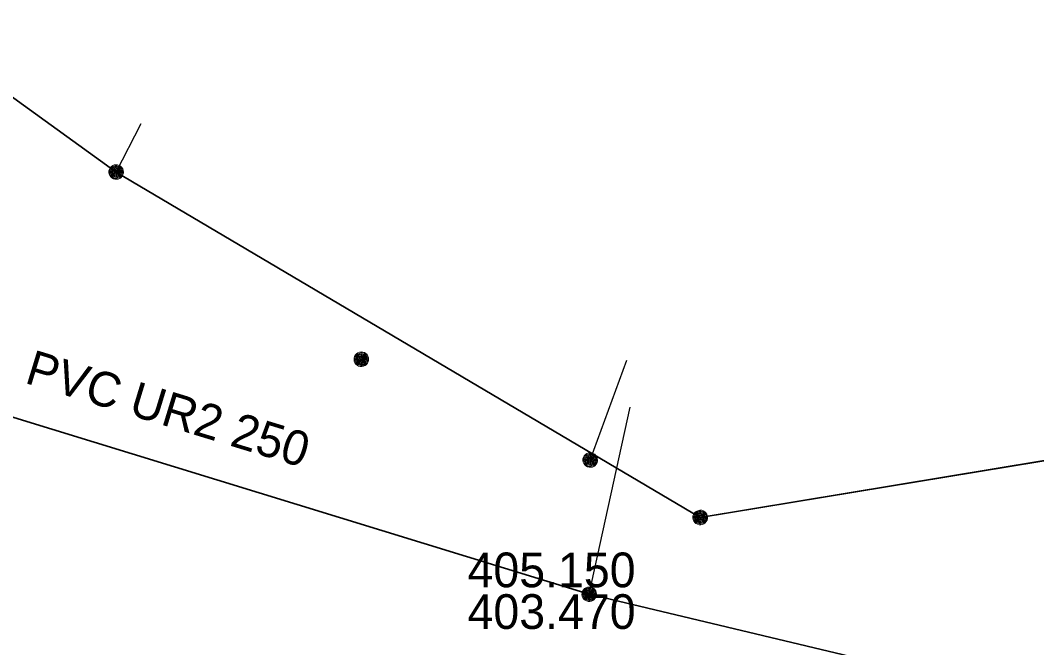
# Model space of a CAD drawing. Extents: x -873619 to -867639, y -1015082 to -1012326.
# Drawn here: x -868080.46 to -868048.3, y -1012848.52 to -1012828.66 of the extents above; entities that cross this region are included whole.
import ezdxf

# ---------------------------------------------------------------- set-up
doc = ezdxf.new("R2010")
doc.units = 0
doc.header["$LTSCALE"] = 0.44
for name, color, linetype, lineweight in [('1', 7, 'Continuous', 13), ('12', 7, 'Continuous', 13), ('21', 7, 'Continuous', 35), ('23', 7, 'Continuous', 25), ('3', 7, 'Continuous', 25), ('32', 7, 'Continuous', 13)]:
    doc.layers.add(name, color=color, linetype=linetype, lineweight=lineweight)

msp = doc.modelspace()

# ---------------------------------------------------------------- linework, layer by layer
at = {"layer": '1', "lineweight": 35}
for points in [[(-867974.611, -1012725.697), (-867976.949, -1012730.385), (-867980.624, -1012763.205), (-867983.112, -1012775.195), (-867978.719, -1012795.525), (-867979.823, -1012805.464), (-867997.768, -1012829.005), (-868011.042, -1012836.499), (-868058.95, -1012844.4), (-868077.43, -1012833.46), (-868085.171, -1012827.86)], [(-868058.95, -1012844.4), (-868077.43, -1012833.46), (-868085.171, -1012827.86), (-868086.94, -1012814.56)], [(-867997.768, -1012829.005), (-868011.041, -1012836.459), (-868058.95, -1012844.4)]]:
    msp.add_lwpolyline(points, dxfattribs=at)
at = {"layer": '12'}
for points in [[(-868077.199, -1012833.46), (-868077.205, -1012833.408), (-868077.222, -1012833.358), (-868077.251, -1012833.314), (-868077.288, -1012833.277), (-868077.333, -1012833.25), (-868077.383, -1012833.233), (-868077.436, -1012833.229), (-868077.488, -1012833.236), (-868077.537, -1012833.255), (-868077.58, -1012833.284), (-868077.616, -1012833.323), (-868077.642, -1012833.368), (-868077.658, -1012833.419), (-868077.661, -1012833.471), (-868077.653, -1012833.523), (-868077.633, -1012833.572), (-868077.602, -1012833.615), (-868077.563, -1012833.649), (-868077.517, -1012833.675), (-868077.466, -1012833.689), (-868077.413, -1012833.691), (-868077.362, -1012833.681), (-868077.314, -1012833.66), (-868077.271, -1012833.629), (-868077.237, -1012833.588), (-868077.213, -1012833.542), (-868077.201, -1012833.491)], [(-868077.229, -1012833.46), (-868077.235, -1012833.411), (-868077.252, -1012833.365), (-868077.28, -1012833.325), (-868077.317, -1012833.293), (-868077.361, -1012833.271), (-868077.409, -1012833.26), (-868077.458, -1012833.26), (-868077.505, -1012833.273), (-868077.548, -1012833.297), (-868077.584, -1012833.33), (-868077.611, -1012833.371), (-868077.627, -1012833.418), (-868077.631, -1012833.467), (-868077.624, -1012833.515), (-868077.605, -1012833.56), (-868077.575, -1012833.6), (-868077.537, -1012833.631), (-868077.493, -1012833.651), (-868077.445, -1012833.661), (-868077.396, -1012833.659), (-868077.349, -1012833.644), (-868077.306, -1012833.619), (-868077.272, -1012833.585), (-868077.246, -1012833.543), (-868077.232, -1012833.496)], [(-868077.259, -1012833.46), (-868077.265, -1012833.415), (-868077.282, -1012833.373), (-868077.31, -1012833.338), (-868077.346, -1012833.311), (-868077.388, -1012833.294), (-868077.433, -1012833.289), (-868077.478, -1012833.295), (-868077.519, -1012833.314), (-868077.554, -1012833.342), (-868077.581, -1012833.379), (-868077.597, -1012833.421), (-868077.601, -1012833.466), (-868077.594, -1012833.511), (-868077.575, -1012833.552), (-868077.546, -1012833.586), (-868077.509, -1012833.612), (-868077.466, -1012833.628), (-868077.421, -1012833.631), (-868077.376, -1012833.623), (-868077.336, -1012833.603), (-868077.302, -1012833.574), (-868077.276, -1012833.536), (-868077.262, -1012833.493)], [(-868077.289, -1012833.46), (-868077.294, -1012833.419), (-868077.312, -1012833.382), (-868077.339, -1012833.351), (-868077.374, -1012833.33), (-868077.414, -1012833.319), (-868077.455, -1012833.321), (-868077.494, -1012833.334), (-868077.528, -1012833.358), (-868077.553, -1012833.39), (-868077.568, -1012833.428), (-868077.571, -1012833.469), (-868077.563, -1012833.509), (-868077.543, -1012833.545), (-868077.514, -1012833.574), (-868077.477, -1012833.593), (-868077.437, -1012833.601), (-868077.396, -1012833.597), (-868077.358, -1012833.582), (-868077.326, -1012833.556), (-868077.303, -1012833.522), (-868077.29, -1012833.483)], [(-868077.319, -1012833.46), (-868077.324, -1012833.424), (-868077.342, -1012833.392), (-868077.368, -1012833.367), (-868077.402, -1012833.352), (-868077.438, -1012833.349), (-868077.473, -1012833.357), (-868077.504, -1012833.377), (-868077.527, -1012833.405), (-868077.54, -1012833.439), (-868077.54, -1012833.476), (-868077.529, -1012833.511), (-868077.508, -1012833.54), (-868077.478, -1012833.561), (-868077.443, -1012833.571), (-868077.406, -1012833.569), (-868077.372, -1012833.555), (-868077.345, -1012833.532), (-868077.326, -1012833.5), (-868077.319, -1012833.465)], [(-868077.349, -1012833.46), (-868077.354, -1012833.429), (-868077.371, -1012833.403), (-868077.397, -1012833.386), (-868077.427, -1012833.379), (-868077.458, -1012833.383), (-868077.485, -1012833.4), (-868077.503, -1012833.424), (-868077.511, -1012833.455), (-868077.507, -1012833.485), (-868077.492, -1012833.513), (-868077.468, -1012833.532), (-868077.438, -1012833.541), (-868077.407, -1012833.538), (-868077.379, -1012833.524), (-868077.359, -1012833.5), (-868077.349, -1012833.471)], [(-868077.379, -1012833.46), (-868077.384, -1012833.436), (-868077.401, -1012833.418), (-868077.424, -1012833.409), (-868077.448, -1012833.412), (-868077.469, -1012833.426), (-868077.48, -1012833.448), (-868077.48, -1012833.473), (-868077.468, -1012833.494), (-868077.448, -1012833.508), (-868077.423, -1012833.511), (-868077.4, -1012833.502), (-868077.384, -1012833.484)], [(-868077.409, -1012833.46), (-868077.414, -1012833.445), (-868077.429, -1012833.439), (-868077.444, -1012833.443), (-868077.451, -1012833.457), (-868077.447, -1012833.472), (-868077.434, -1012833.481), (-868077.419, -1012833.478), (-868077.409, -1012833.466)], [(-868062.199, -1012842.58), (-868062.205, -1012842.528), (-868062.222, -1012842.478), (-868062.251, -1012842.434), (-868062.288, -1012842.397), (-868062.333, -1012842.37), (-868062.383, -1012842.353), (-868062.436, -1012842.349), (-868062.488, -1012842.356), (-868062.537, -1012842.375), (-868062.58, -1012842.404), (-868062.616, -1012842.443), (-868062.642, -1012842.488), (-868062.658, -1012842.539), (-868062.661, -1012842.591), (-868062.653, -1012842.643), (-868062.633, -1012842.692), (-868062.602, -1012842.735), (-868062.563, -1012842.769), (-868062.517, -1012842.795), (-868062.466, -1012842.809), (-868062.413, -1012842.811), (-868062.362, -1012842.801), (-868062.314, -1012842.78), (-868062.271, -1012842.749), (-868062.237, -1012842.708), (-868062.213, -1012842.662), (-868062.201, -1012842.611)], [(-868062.229, -1012842.58), (-868062.235, -1012842.531), (-868062.252, -1012842.485), (-868062.28, -1012842.445), (-868062.317, -1012842.413), (-868062.361, -1012842.391), (-868062.409, -1012842.38), (-868062.458, -1012842.38), (-868062.505, -1012842.393), (-868062.548, -1012842.417), (-868062.584, -1012842.45), (-868062.611, -1012842.491), (-868062.627, -1012842.538), (-868062.631, -1012842.587), (-868062.624, -1012842.635), (-868062.605, -1012842.68), (-868062.575, -1012842.72), (-868062.537, -1012842.751), (-868062.493, -1012842.771), (-868062.445, -1012842.781), (-868062.396, -1012842.779), (-868062.349, -1012842.764), (-868062.306, -1012842.739), (-868062.272, -1012842.705), (-868062.246, -1012842.663), (-868062.232, -1012842.616)], [(-868062.259, -1012842.58), (-868062.265, -1012842.535), (-868062.282, -1012842.493), (-868062.31, -1012842.458), (-868062.346, -1012842.431), (-868062.388, -1012842.414), (-868062.433, -1012842.409), (-868062.478, -1012842.415), (-868062.519, -1012842.434), (-868062.554, -1012842.462), (-868062.581, -1012842.499), (-868062.597, -1012842.541), (-868062.601, -1012842.586), (-868062.594, -1012842.631), (-868062.575, -1012842.672), (-868062.546, -1012842.706), (-868062.509, -1012842.732), (-868062.466, -1012842.748), (-868062.421, -1012842.751), (-868062.376, -1012842.743), (-868062.336, -1012842.723), (-868062.302, -1012842.694), (-868062.276, -1012842.656), (-868062.262, -1012842.613)], [(-868062.289, -1012842.58), (-868062.294, -1012842.539), (-868062.312, -1012842.502), (-868062.339, -1012842.471), (-868062.374, -1012842.45), (-868062.414, -1012842.439), (-868062.455, -1012842.441), (-868062.494, -1012842.454), (-868062.528, -1012842.478), (-868062.553, -1012842.51), (-868062.568, -1012842.548), (-868062.571, -1012842.589), (-868062.563, -1012842.629), (-868062.543, -1012842.665), (-868062.514, -1012842.694), (-868062.477, -1012842.713), (-868062.437, -1012842.721), (-868062.396, -1012842.717), (-868062.358, -1012842.702), (-868062.326, -1012842.676), (-868062.303, -1012842.642), (-868062.29, -1012842.603)], [(-868062.319, -1012842.58), (-868062.324, -1012842.544), (-868062.342, -1012842.512), (-868062.368, -1012842.487), (-868062.402, -1012842.472), (-868062.438, -1012842.469), (-868062.473, -1012842.477), (-868062.504, -1012842.497), (-868062.527, -1012842.525), (-868062.54, -1012842.559), (-868062.54, -1012842.596), (-868062.529, -1012842.631), (-868062.508, -1012842.66), (-868062.478, -1012842.681), (-868062.443, -1012842.691), (-868062.406, -1012842.689), (-868062.372, -1012842.675), (-868062.345, -1012842.652), (-868062.326, -1012842.62), (-868062.319, -1012842.585)], [(-868062.349, -1012842.58), (-868062.354, -1012842.549), (-868062.371, -1012842.523), (-868062.397, -1012842.506), (-868062.427, -1012842.499), (-868062.458, -1012842.503), (-868062.485, -1012842.52), (-868062.503, -1012842.544), (-868062.511, -1012842.575), (-868062.507, -1012842.605), (-868062.492, -1012842.633), (-868062.468, -1012842.652), (-868062.438, -1012842.661), (-868062.407, -1012842.658), (-868062.379, -1012842.644), (-868062.359, -1012842.62), (-868062.349, -1012842.591)], [(-868062.379, -1012842.58), (-868062.384, -1012842.556), (-868062.401, -1012842.538), (-868062.424, -1012842.529), (-868062.448, -1012842.532), (-868062.469, -1012842.546), (-868062.48, -1012842.568), (-868062.48, -1012842.593), (-868062.468, -1012842.614), (-868062.448, -1012842.628), (-868062.423, -1012842.631), (-868062.4, -1012842.622), (-868062.384, -1012842.604)], [(-868062.409, -1012842.58), (-868062.414, -1012842.565), (-868062.429, -1012842.559), (-868062.444, -1012842.563), (-868062.451, -1012842.577), (-868062.447, -1012842.592), (-868062.434, -1012842.601), (-868062.419, -1012842.598), (-868062.409, -1012842.586)], [(-868058.718, -1012844.4), (-868058.725, -1012844.348), (-868058.742, -1012844.298), (-868058.771, -1012844.254), (-868058.808, -1012844.217), (-868058.853, -1012844.19), (-868058.902, -1012844.173), (-868058.956, -1012844.169), (-868059.007, -1012844.176), (-868059.056, -1012844.195), (-868059.1, -1012844.224), (-868059.136, -1012844.263), (-868059.162, -1012844.308), (-868059.178, -1012844.359), (-868059.181, -1012844.411), (-868059.173, -1012844.463), (-868059.152, -1012844.512), (-868059.122, -1012844.555), (-868059.083, -1012844.589), (-868059.037, -1012844.615), (-868058.985, -1012844.629), (-868058.933, -1012844.631), (-868058.882, -1012844.621), (-868058.833, -1012844.6), (-868058.791, -1012844.569), (-868058.757, -1012844.528), (-868058.733, -1012844.482), (-868058.72, -1012844.431)], [(-868058.749, -1012844.4), (-868058.755, -1012844.351), (-868058.772, -1012844.305), (-868058.799, -1012844.265), (-868058.837, -1012844.233), (-868058.88, -1012844.211), (-868058.929, -1012844.2), (-868058.978, -1012844.2), (-868059.024, -1012844.213), (-868059.068, -1012844.237), (-868059.103, -1012844.27), (-868059.13, -1012844.311), (-868059.147, -1012844.358), (-868059.151, -1012844.407), (-868059.144, -1012844.455), (-868059.125, -1012844.5), (-868059.095, -1012844.54), (-868059.056, -1012844.571), (-868059.012, -1012844.591), (-868058.965, -1012844.601), (-868058.916, -1012844.599), (-868058.869, -1012844.584), (-868058.826, -1012844.559), (-868058.791, -1012844.525), (-868058.766, -1012844.483), (-868058.752, -1012844.436)], [(-868058.779, -1012844.4), (-868058.784, -1012844.355), (-868058.801, -1012844.313), (-868058.83, -1012844.278), (-868058.865, -1012844.251), (-868058.907, -1012844.234), (-868058.953, -1012844.229), (-868058.997, -1012844.235), (-868059.039, -1012844.254), (-868059.073, -1012844.282), (-868059.1, -1012844.319), (-868059.117, -1012844.361), (-868059.12, -1012844.406), (-868059.114, -1012844.451), (-868059.095, -1012844.492), (-868059.066, -1012844.526), (-868059.029, -1012844.552), (-868058.985, -1012844.568), (-868058.941, -1012844.571), (-868058.896, -1012844.563), (-868058.855, -1012844.543), (-868058.821, -1012844.514), (-868058.796, -1012844.476), (-868058.782, -1012844.433)], [(-868058.809, -1012844.4), (-868058.813, -1012844.359), (-868058.831, -1012844.322), (-868058.858, -1012844.291), (-868058.894, -1012844.27), (-868058.934, -1012844.259), (-868058.975, -1012844.261), (-868059.014, -1012844.274), (-868059.048, -1012844.298), (-868059.073, -1012844.33), (-868059.088, -1012844.368), (-868059.09, -1012844.409), (-868059.083, -1012844.449), (-868059.063, -1012844.485), (-868059.034, -1012844.514), (-868058.997, -1012844.533), (-868058.956, -1012844.541), (-868058.916, -1012844.537), (-868058.877, -1012844.522), (-868058.845, -1012844.496), (-868058.823, -1012844.462), (-868058.809, -1012844.423)], [(-868058.838, -1012844.4), (-868058.843, -1012844.364), (-868058.862, -1012844.332), (-868058.887, -1012844.307), (-868058.921, -1012844.292), (-868058.958, -1012844.289), (-868058.992, -1012844.297), (-868059.024, -1012844.317), (-868059.046, -1012844.345), (-868059.059, -1012844.379), (-868059.059, -1012844.416), (-868059.049, -1012844.451), (-868059.027, -1012844.48), (-868058.997, -1012844.501), (-868058.963, -1012844.511), (-868058.926, -1012844.509), (-868058.892, -1012844.495), (-868058.865, -1012844.472), (-868058.845, -1012844.44), (-868058.838, -1012844.405)], [(-868058.869, -1012844.4), (-868058.874, -1012844.369), (-868058.891, -1012844.343), (-868058.916, -1012844.326), (-868058.946, -1012844.319), (-868058.978, -1012844.323), (-868059.005, -1012844.34), (-868059.022, -1012844.364), (-868059.031, -1012844.395), (-868059.027, -1012844.425), (-868059.012, -1012844.453), (-868058.987, -1012844.472), (-868058.958, -1012844.481), (-868058.926, -1012844.478), (-868058.899, -1012844.464), (-868058.879, -1012844.44), (-868058.869, -1012844.411)], [(-868058.899, -1012844.4), (-868058.904, -1012844.376), (-868058.921, -1012844.358), (-868058.943, -1012844.349), (-868058.968, -1012844.352), (-868058.989, -1012844.366), (-868059, -1012844.388), (-868059, -1012844.413), (-868058.987, -1012844.434), (-868058.968, -1012844.448), (-868058.943, -1012844.451), (-868058.919, -1012844.442), (-868058.904, -1012844.424)], [(-868058.929, -1012844.4), (-868058.934, -1012844.385), (-868058.948, -1012844.379), (-868058.963, -1012844.383), (-868058.97, -1012844.397), (-868058.967, -1012844.412), (-868058.953, -1012844.421), (-868058.938, -1012844.418), (-868058.929, -1012844.406)]]:
    msp.add_lwpolyline(points, close=True, dxfattribs=at)
at = {"layer": '21'}
msp.add_lwpolyline([(-868134.19, -1012752.63), (-868112.27, -1012769.62), (-868107.42, -1012773.25), (-868101.75, -1012777.58), (-868093.15, -1012793.25), (-868087.37, -1012839.18), (-868062.459, -1012846.83), (-868020.28, -1012856.9)], dxfattribs=at)
at = {"layer": '23'}
msp.add_line((-868062.459, -1012846.83), (-868061.17, -1012840.91), dxfattribs=at)
at = {"layer": '3'}
for p, q in [((-868077.43, -1012833.46), (-868076.634, -1012831.92)), ((-868062.43, -1012842.58), (-868061.266, -1012839.421))]:
    msp.add_line(p, q, dxfattribs=at)
at = {"layer": '32'}
for points in [[(-868069.44, -1012839.389), (-868069.446, -1012839.337), (-868069.463, -1012839.287), (-868069.492, -1012839.243), (-868069.529, -1012839.206), (-868069.574, -1012839.179), (-868069.624, -1012839.162), (-868069.677, -1012839.158), (-868069.728, -1012839.165), (-868069.777, -1012839.184), (-868069.821, -1012839.213), (-868069.857, -1012839.252), (-868069.883, -1012839.297), (-868069.899, -1012839.348), (-868069.902, -1012839.4), (-868069.894, -1012839.452), (-868069.874, -1012839.501), (-868069.843, -1012839.544), (-868069.804, -1012839.578), (-868069.758, -1012839.604), (-868069.706, -1012839.618), (-868069.654, -1012839.62), (-868069.603, -1012839.61), (-868069.554, -1012839.589), (-868069.512, -1012839.558), (-868069.478, -1012839.517), (-868069.454, -1012839.471), (-868069.441, -1012839.42)], [(-868069.47, -1012839.389), (-868069.476, -1012839.34), (-868069.493, -1012839.294), (-868069.521, -1012839.254), (-868069.558, -1012839.222), (-868069.602, -1012839.2), (-868069.65, -1012839.189), (-868069.699, -1012839.189), (-868069.745, -1012839.202), (-868069.789, -1012839.226), (-868069.825, -1012839.259), (-868069.852, -1012839.3), (-868069.868, -1012839.347), (-868069.872, -1012839.396), (-868069.865, -1012839.444), (-868069.846, -1012839.489), (-868069.816, -1012839.529), (-868069.777, -1012839.56), (-868069.733, -1012839.58), (-868069.686, -1012839.59), (-868069.637, -1012839.588), (-868069.59, -1012839.573), (-868069.547, -1012839.548), (-868069.512, -1012839.514), (-868069.487, -1012839.472), (-868069.473, -1012839.425)], [(-868069.5, -1012839.389), (-868069.505, -1012839.344), (-868069.522, -1012839.302), (-868069.551, -1012839.267), (-868069.587, -1012839.24), (-868069.629, -1012839.223), (-868069.674, -1012839.218), (-868069.718, -1012839.224), (-868069.76, -1012839.243), (-868069.794, -1012839.271), (-868069.821, -1012839.308), (-868069.838, -1012839.35), (-868069.842, -1012839.395), (-868069.835, -1012839.44), (-868069.816, -1012839.481), (-868069.787, -1012839.515), (-868069.75, -1012839.541), (-868069.706, -1012839.557), (-868069.662, -1012839.56), (-868069.617, -1012839.552), (-868069.576, -1012839.532), (-868069.543, -1012839.503), (-868069.517, -1012839.465), (-868069.503, -1012839.422)], [(-868069.53, -1012839.389), (-868069.534, -1012839.348), (-868069.553, -1012839.311), (-868069.58, -1012839.28), (-868069.615, -1012839.259), (-868069.655, -1012839.248), (-868069.696, -1012839.25), (-868069.735, -1012839.263), (-868069.769, -1012839.287), (-868069.794, -1012839.319), (-868069.809, -1012839.357), (-868069.811, -1012839.398), (-868069.804, -1012839.438), (-868069.784, -1012839.474), (-868069.755, -1012839.503), (-868069.718, -1012839.522), (-868069.678, -1012839.53), (-868069.637, -1012839.526), (-868069.598, -1012839.511), (-868069.566, -1012839.485), (-868069.544, -1012839.451), (-868069.531, -1012839.412)], [(-868069.559, -1012839.389), (-868069.565, -1012839.353), (-868069.583, -1012839.321), (-868069.608, -1012839.296), (-868069.642, -1012839.281), (-868069.679, -1012839.278), (-868069.713, -1012839.286), (-868069.745, -1012839.306), (-868069.767, -1012839.334), (-868069.781, -1012839.368), (-868069.781, -1012839.405), (-868069.77, -1012839.44), (-868069.749, -1012839.469), (-868069.718, -1012839.49), (-868069.684, -1012839.5), (-868069.647, -1012839.498), (-868069.613, -1012839.484), (-868069.586, -1012839.461), (-868069.566, -1012839.429), (-868069.559, -1012839.394)], [(-868069.59, -1012839.389), (-868069.595, -1012839.358), (-868069.612, -1012839.332), (-868069.637, -1012839.315), (-868069.668, -1012839.308), (-868069.699, -1012839.312), (-868069.726, -1012839.329), (-868069.744, -1012839.353), (-868069.752, -1012839.384), (-868069.748, -1012839.414), (-868069.733, -1012839.442), (-868069.708, -1012839.461), (-868069.679, -1012839.47), (-868069.647, -1012839.467), (-868069.62, -1012839.453), (-868069.6, -1012839.429), (-868069.59, -1012839.4)], [(-868069.62, -1012839.389), (-868069.625, -1012839.365), (-868069.642, -1012839.347), (-868069.664, -1012839.338), (-868069.689, -1012839.341), (-868069.71, -1012839.355), (-868069.721, -1012839.377), (-868069.721, -1012839.402), (-868069.708, -1012839.423), (-868069.689, -1012839.437), (-868069.664, -1012839.44), (-868069.641, -1012839.431), (-868069.625, -1012839.413)], [(-868069.65, -1012839.389), (-868069.655, -1012839.374), (-868069.669, -1012839.368), (-868069.684, -1012839.372), (-868069.691, -1012839.386), (-868069.688, -1012839.401), (-868069.674, -1012839.41), (-868069.659, -1012839.407), (-868069.65, -1012839.395)], [(-868062.23, -1012846.829), (-868062.236, -1012846.777), (-868062.253, -1012846.727), (-868062.282, -1012846.683), (-868062.319, -1012846.646), (-868062.364, -1012846.619), (-868062.414, -1012846.602), (-868062.467, -1012846.598), (-868062.519, -1012846.605), (-868062.568, -1012846.624), (-868062.611, -1012846.653), (-868062.647, -1012846.692), (-868062.673, -1012846.737), (-868062.689, -1012846.788), (-868062.692, -1012846.84), (-868062.684, -1012846.892), (-868062.664, -1012846.941), (-868062.633, -1012846.984), (-868062.594, -1012847.018), (-868062.548, -1012847.044), (-868062.497, -1012847.058), (-868062.444, -1012847.06), (-868062.393, -1012847.05), (-868062.345, -1012847.029), (-868062.302, -1012846.998), (-868062.268, -1012846.957), (-868062.244, -1012846.911), (-868062.232, -1012846.86)], [(-868062.26, -1012846.829), (-868062.266, -1012846.78), (-868062.283, -1012846.734), (-868062.311, -1012846.694), (-868062.348, -1012846.662), (-868062.392, -1012846.64), (-868062.44, -1012846.629), (-868062.489, -1012846.629), (-868062.536, -1012846.642), (-868062.579, -1012846.666), (-868062.615, -1012846.699), (-868062.642, -1012846.74), (-868062.658, -1012846.787), (-868062.662, -1012846.836), (-868062.655, -1012846.884), (-868062.636, -1012846.929), (-868062.606, -1012846.969), (-868062.568, -1012847), (-868062.524, -1012847.02), (-868062.476, -1012847.03), (-868062.427, -1012847.028), (-868062.38, -1012847.013), (-868062.337, -1012846.988), (-868062.303, -1012846.954), (-868062.277, -1012846.912), (-868062.263, -1012846.865)], [(-868062.29, -1012846.829), (-868062.296, -1012846.784), (-868062.313, -1012846.742), (-868062.341, -1012846.707), (-868062.377, -1012846.68), (-868062.419, -1012846.663), (-868062.464, -1012846.658), (-868062.509, -1012846.664), (-868062.55, -1012846.683), (-868062.585, -1012846.711), (-868062.612, -1012846.748), (-868062.628, -1012846.79), (-868062.632, -1012846.835), (-868062.625, -1012846.88), (-868062.606, -1012846.921), (-868062.577, -1012846.955), (-868062.54, -1012846.981), (-868062.497, -1012846.997), (-868062.452, -1012847), (-868062.407, -1012846.992), (-868062.367, -1012846.972), (-868062.333, -1012846.943), (-868062.307, -1012846.905), (-868062.293, -1012846.862)], [(-868062.32, -1012846.829), (-868062.325, -1012846.788), (-868062.343, -1012846.751), (-868062.37, -1012846.72), (-868062.405, -1012846.699), (-868062.445, -1012846.688), (-868062.486, -1012846.69), (-868062.525, -1012846.703), (-868062.559, -1012846.727), (-868062.584, -1012846.759), (-868062.599, -1012846.797), (-868062.602, -1012846.838), (-868062.594, -1012846.878), (-868062.574, -1012846.914), (-868062.545, -1012846.943), (-868062.508, -1012846.962), (-868062.468, -1012846.97), (-868062.427, -1012846.966), (-868062.389, -1012846.951), (-868062.357, -1012846.925), (-868062.334, -1012846.891), (-868062.321, -1012846.852)], [(-868062.35, -1012846.829), (-868062.355, -1012846.793), (-868062.373, -1012846.761), (-868062.399, -1012846.736), (-868062.433, -1012846.721), (-868062.469, -1012846.718), (-868062.504, -1012846.726), (-868062.535, -1012846.746), (-868062.558, -1012846.774), (-868062.571, -1012846.808), (-868062.571, -1012846.845), (-868062.56, -1012846.88), (-868062.539, -1012846.909), (-868062.509, -1012846.93), (-868062.474, -1012846.94), (-868062.437, -1012846.938), (-868062.403, -1012846.924), (-868062.376, -1012846.901), (-868062.357, -1012846.869), (-868062.35, -1012846.834)], [(-868062.38, -1012846.829), (-868062.385, -1012846.798), (-868062.402, -1012846.772), (-868062.428, -1012846.755), (-868062.458, -1012846.748), (-868062.489, -1012846.752), (-868062.516, -1012846.769), (-868062.534, -1012846.793), (-868062.542, -1012846.824), (-868062.538, -1012846.854), (-868062.523, -1012846.882), (-868062.499, -1012846.901), (-868062.469, -1012846.91), (-868062.438, -1012846.907), (-868062.41, -1012846.893), (-868062.39, -1012846.869), (-868062.38, -1012846.84)], [(-868062.41, -1012846.829), (-868062.415, -1012846.805), (-868062.432, -1012846.787), (-868062.455, -1012846.778), (-868062.479, -1012846.781), (-868062.5, -1012846.795), (-868062.511, -1012846.817), (-868062.511, -1012846.842), (-868062.499, -1012846.863), (-868062.479, -1012846.877), (-868062.454, -1012846.88), (-868062.431, -1012846.871), (-868062.415, -1012846.853)], [(-868062.44, -1012846.829), (-868062.445, -1012846.814), (-868062.46, -1012846.808), (-868062.475, -1012846.812), (-868062.482, -1012846.826), (-868062.478, -1012846.841), (-868062.465, -1012846.85), (-868062.45, -1012846.847), (-868062.44, -1012846.835)]]:
    msp.add_lwpolyline(points, close=True, dxfattribs=at)

# ---------------------------------------------------------------- texts
at = {"layer": '1'}
msp.add_text('PVC UR2 250 ', height=1.1, rotation=343, dxfattribs=at).set_placement((-868080.359, -1012840.128))
for s, p in [('405.150 ', (-868066.311, -1012846.609)), ('403.470 ', (-868066.311, -1012847.929))]:
    msp.add_text(s, height=1.1, dxfattribs=at).set_placement(p)

doc.saveas('drawing.dxf')
